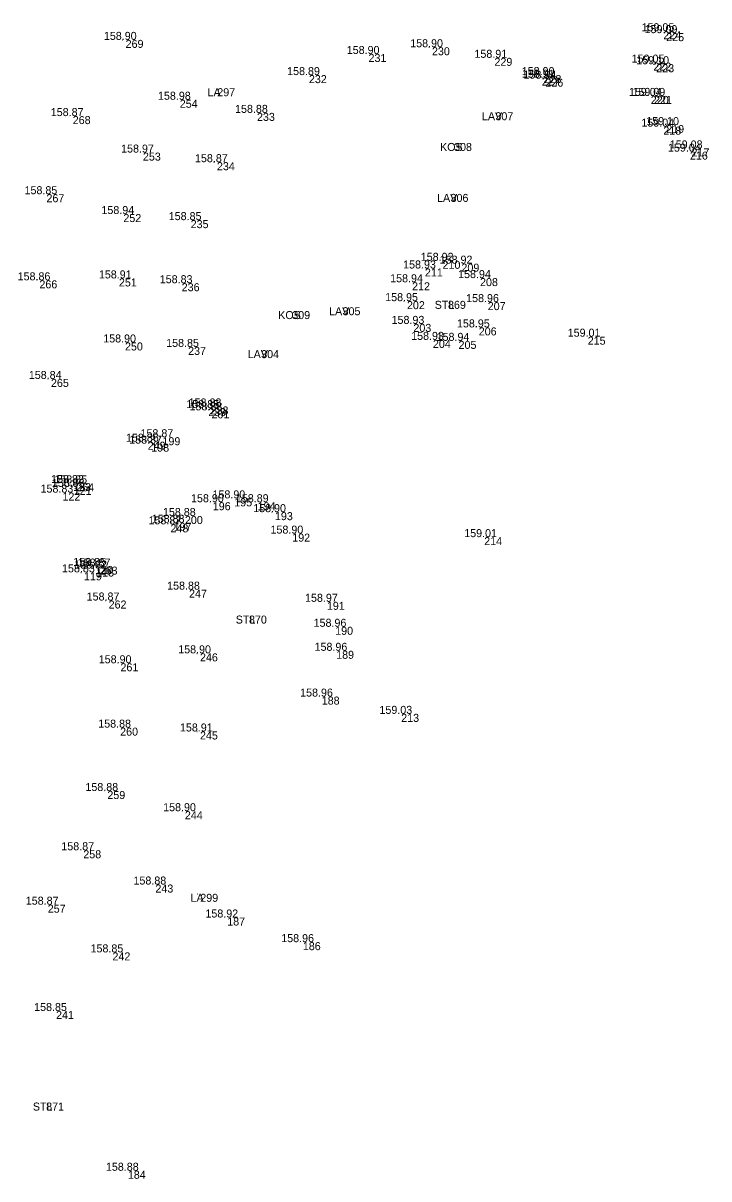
# Model space of a CAD drawing. Extents: x -583198 to -582878, y -1211024 to -1210637.
# Drawn here: x -583157.8 to -583136.4, y -1210989.52 to -1210953.43 of the extents above; entities that cross this region are included whole.
import ezdxf

# ---------------------------------------------------------------- set-up
doc = ezdxf.new("R2010")
doc.units = 0
for name, color, linetype in [('1   Kódy', 7, 'Continuous'), ('4   Body podrobné', 7, 'Continuous'), ('5   Body podrobné - čísla', 7, 'Continuous'), ('6   Body podrobné - výšky', 7, 'Continuous')]:
    doc.layers.add(name, color=color, linetype=linetype)

msp = doc.modelspace()

# ---------------------------------------------------------------- linework, layer by layer
at = {"layer": '4   Body podrobné'}
for p, q in [((-583137.91, -1210953.68), (-583137.909, -1210953.68)), ((-583137.82, -1210953.74), (-583137.819, -1210953.74)), ((-583154.69, -1210953.95), (-583154.689, -1210953.95)), ((-583145.13, -1210954.18), (-583145.129, -1210954.18)), ((-583147.11, -1210954.39), (-583147.109, -1210954.39)), ((-583143.18, -1210954.51), (-583143.179, -1210954.51)), ((-583138.22, -1210954.66), (-583138.219, -1210954.66)), ((-583138.13, -1210954.71), (-583138.129, -1210954.71)), ((-583148.97, -1210955.05), (-583148.969, -1210955.05)), ((-583141.7, -1210955.13), (-583141.699, -1210955.13)), ((-583141.65, -1210955.05), (-583141.649, -1210955.05)), ((-583141.59, -1210955.16), (-583141.589, -1210955.16)), ((-583151.83, -1210955.46), (-583151.829, -1210955.46)), ((-583153, -1210955.82), (-583152.999, -1210955.82)), ((-583138.3, -1210955.7), (-583138.299, -1210955.7)), ((-583138.2, -1210955.7), (-583138.199, -1210955.7)), ((-583156.34, -1210956.33), (-583156.339, -1210956.33)), ((-583150.59, -1210956.23), (-583150.589, -1210956.23)), ((-583143.15, -1210956.21), (-583143.149, -1210956.21)), ((-583137.91, -1210956.66), (-583137.909, -1210956.66)), ((-583137.82, -1210956.61), (-583137.819, -1210956.61)), ((-583144.44, -1210957.17), (-583144.439, -1210957.17)), ((-583137.03, -1210957.34), (-583137.029, -1210957.34)), ((-583154.15, -1210957.47), (-583154.149, -1210957.47)), ((-583151.84, -1210957.77), (-583151.839, -1210957.77)), ((-583137.08, -1210957.44), (-583137.079, -1210957.44)), ((-583157.16, -1210958.77), (-583157.159, -1210958.77)), ((-583144.55, -1210958.76), (-583144.549, -1210958.76)), ((-583154.76, -1210959.39), (-583154.759, -1210959.39)), ((-583152.66, -1210959.58), (-583152.659, -1210959.58)), ((-583144.8, -1210960.85), (-583144.799, -1210960.85)), ((-583144.21, -1210960.94), (-583144.209, -1210960.94)), ((-583154.9, -1210961.4), (-583154.899, -1210961.4)), ((-583145.35, -1210961.09), (-583145.349, -1210961.09)), ((-583143.63, -1210961.39), (-583143.629, -1210961.39)), ((-583157.38, -1210961.46), (-583157.379, -1210961.46)), ((-583152.94, -1210961.55), (-583152.939, -1210961.55)), ((-583145.75, -1210961.52), (-583145.749, -1210961.52)), ((-583145.91, -1210962.11), (-583145.909, -1210962.11)), ((-583144.63, -1210962.1), (-583144.629, -1210962.1)), ((-583149.49, -1210962.42), (-583149.489, -1210962.42)), ((-583147.92, -1210962.3), (-583147.919, -1210962.3)), ((-583143.39, -1210962.14), (-583143.389, -1210962.14)), ((-583145.71, -1210962.82), (-583145.709, -1210962.82)), ((-583143.67, -1210962.93), (-583143.669, -1210962.93)), ((-583154.71, -1210963.4), (-583154.709, -1210963.4)), ((-583152.74, -1210963.54), (-583152.739, -1210963.54)), ((-583145.1, -1210963.32), (-583145.099, -1210963.32)), ((-583144.3, -1210963.35), (-583144.299, -1210963.35)), ((-583140.27, -1210963.22), (-583140.269, -1210963.22)), ((-583150.46, -1210963.64), (-583150.459, -1210963.64)), ((-583157.02, -1210964.54), (-583157.019, -1210964.54)), ((-583152.11, -1210965.45), (-583152.109, -1210965.45)), ((-583152.04, -1210965.4), (-583152.039, -1210965.4)), ((-583152.01, -1210965.52), (-583152.009, -1210965.52)), ((-583153.54, -1210966.36), (-583153.539, -1210966.36)), ((-583154, -1210966.5), (-583153.999, -1210966.5)), ((-583153.89, -1210966.56), (-583153.889, -1210966.56)), ((-583156.33, -1210967.79), (-583156.329, -1210967.79)), ((-583156.23, -1210967.8), (-583156.229, -1210967.8)), ((-583156.66, -1210968.09), (-583156.659, -1210968.09)), ((-583156.31, -1210967.91), (-583156.309, -1210967.91)), ((-583151.97, -1210968.39), (-583151.969, -1210968.39)), ((-583151.3, -1210968.27), (-583151.299, -1210968.27)), ((-583150.57, -1210968.39), (-583150.569, -1210968.39)), ((-583152.84, -1210968.82), (-583152.839, -1210968.82)), ((-583150.03, -1210968.7), (-583150.029, -1210968.7)), ((-583153.29, -1210969.08), (-583153.289, -1210969.08)), ((-583153.19, -1210969.03), (-583153.189, -1210969.03)), ((-583149.49, -1210969.37), (-583149.489, -1210969.37)), ((-583143.5, -1210969.48), (-583143.499, -1210969.48)), ((-583155.64, -1210970.38), (-583155.639, -1210970.38)), ((-583155.5, -1210970.4), (-583155.499, -1210970.4)), ((-583155.99, -1210970.58), (-583155.989, -1210970.58)), ((-583155.61, -1210970.46), (-583155.609, -1210970.46)), ((-583152.71, -1210971.12), (-583152.709, -1210971.12)), ((-583155.22, -1210971.46), (-583155.219, -1210971.46)), ((-583148.41, -1210971.5), (-583148.409, -1210971.5)), ((-583150.84, -1210971.93), (-583150.839, -1210971.93)), ((-583148.15, -1210972.28), (-583148.149, -1210972.28)), ((-583152.37, -1210973.11), (-583152.369, -1210973.11)), ((-583148.12, -1210973.03), (-583148.119, -1210973.03)), ((-583154.85, -1210973.42), (-583154.849, -1210973.42)), ((-583148.57, -1210974.46), (-583148.569, -1210974.46)), ((-583146.09, -1210975), (-583146.089, -1210975)), ((-583154.86, -1210975.43), (-583154.859, -1210975.43)), ((-583152.37, -1210975.55), (-583152.369, -1210975.55)), ((-583155.26, -1210977.41), (-583155.259, -1210977.41)), ((-583152.84, -1210978.04), (-583152.839, -1210978.04)), ((-583156.01, -1210979.26), (-583156.009, -1210979.26)), ((-583153.76, -1210980.33), (-583153.759, -1210980.33)), ((-583152.36, -1210980.62), (-583152.359, -1210980.62)), ((-583157.12, -1210980.96), (-583157.119, -1210980.96)), ((-583151.52, -1210981.36), (-583151.519, -1210981.36)), ((-583149.16, -1210982.13), (-583149.159, -1210982.13)), ((-583155.1, -1210982.45), (-583155.099, -1210982.45)), ((-583156.86, -1210984.28), (-583156.859, -1210984.28)), ((-583157.17, -1210987.14), (-583157.169, -1210987.14)), ((-583154.62, -1210989.27), (-583154.619, -1210989.27))]:
    msp.add_line(p, q, dxfattribs=at)

# ---------------------------------------------------------------- texts
at = {"layer": '1   Kódy'}
for s, p in [('LA', (-583152.04, -1210955.71)), ('LAV', (-583143.478, -1210956.46)), ('KOS', (-583144.785, -1210957.42)), ('LAV', (-583144.878, -1210959.01)), ('STL', (-583144.952, -1210962.35)), ('KOS', (-583149.835, -1210962.67)), ('LAV', (-583148.248, -1210962.55)), ('LAV', (-583150.788, -1210963.89)), ('STL', (-583151.162, -1210972.18)), ('LA', (-583152.57, -1210980.87)), ('STL', (-583157.492, -1210987.39))]:
    msp.add_text(s, height=0.25, dxfattribs=at).set_placement(p)
at = {"layer": '5   Body podrobné - čísla'}
for s, p in [(' 224', (-583137.91, -1210953.93)), (' 225', (-583137.82, -1210953.99)), (' 269', (-583154.69, -1210954.2)), (' 230', (-583145.13, -1210954.43)), (' 231', (-583147.11, -1210954.64)), (' 229', (-583143.18, -1210954.76)), (' 222', (-583138.22, -1210954.91)), (' 223', (-583138.13, -1210954.96)), (' 232', (-583148.97, -1210955.3)), (' 227', (-583141.7, -1210955.38)), (' 228', (-583141.65, -1210955.3)), (' 226', (-583141.59, -1210955.41)), (' 297', (-583151.83, -1210955.71)), (' 254', (-583153, -1210956.07)), (' 220', (-583138.3, -1210955.95)), (' 221', (-583138.2, -1210955.95)), (' 268', (-583156.34, -1210956.58)), (' 233', (-583150.59, -1210956.48)), (' 307', (-583143.15, -1210956.46)), (' 218', (-583137.91, -1210956.91)), (' 219', (-583137.82, -1210956.86)), (' 308', (-583144.44, -1210957.42)), (' 216', (-583137.08, -1210957.69)), (' 217', (-583137.03, -1210957.59)), (' 253', (-583154.15, -1210957.72)), (' 234', (-583151.84, -1210958.02)), (' 267', (-583157.16, -1210959.02)), (' 306', (-583144.55, -1210959.01)), (' 252', (-583154.76, -1210959.64)), (' 235', (-583152.66, -1210959.83)), (' 210', (-583144.8, -1210961.1)), (' 209', (-583144.21, -1210961.19)), (' 251', (-583154.9, -1210961.65)), (' 211', (-583145.35, -1210961.34)), (' 208', (-583143.63, -1210961.64)), (' 266', (-583157.38, -1210961.71)), (' 236', (-583152.94, -1210961.8)), (' 212', (-583145.75, -1210961.77)), (' 202', (-583145.91, -1210962.36)), (' 869', (-583144.63, -1210962.35)), (' 309', (-583149.49, -1210962.67)), (' 305', (-583147.92, -1210962.55)), (' 207', (-583143.39, -1210962.39)), (' 203', (-583145.71, -1210963.07)), (' 206', (-583143.67, -1210963.18)), (' 250', (-583154.71, -1210963.65)), (' 237', (-583152.74, -1210963.79)), (' 204', (-583145.1, -1210963.57)), (' 205', (-583144.3, -1210963.6)), (' 215', (-583140.27, -1210963.47)), (' 304', (-583150.46, -1210963.89)), (' 265', (-583157.02, -1210964.79)), (' 239', (-583152.11, -1210965.7)), (' 238', (-583152.04, -1210965.65)), (' 201', (-583152.01, -1210965.77)), (' 199', (-583153.54, -1210966.61)), (' 249', (-583154, -1210966.75)), (' 198', (-583153.89, -1210966.81)), (' 123', (-583156.33, -1210968.04)), (' 121', (-583156.31, -1210968.16)), (' 264', (-583156.23, -1210968.05)), (' 122', (-583156.66, -1210968.34)), (' 195', (-583151.3, -1210968.52)), (' 196', (-583151.97, -1210968.64)), (' 194', (-583150.57, -1210968.64)), (' 200', (-583152.84, -1210969.07)), (' 193', (-583150.03, -1210968.95)), (' 248', (-583153.29, -1210969.33)), (' 197', (-583153.19, -1210969.28)), (' 192', (-583149.49, -1210969.62)), (' 214', (-583143.5, -1210969.73)), (' 120', (-583155.64, -1210970.63)), (' 263', (-583155.5, -1210970.65)), (' 119', (-583155.99, -1210970.83)), (' 118', (-583155.61, -1210970.71)), (' 247', (-583152.71, -1210971.37)), (' 262', (-583155.22, -1210971.71)), (' 191', (-583148.41, -1210971.75)), (' 870', (-583150.84, -1210972.18)), (' 190', (-583148.15, -1210972.53)), (' 246', (-583152.37, -1210973.36)), (' 189', (-583148.12, -1210973.28)), (' 261', (-583154.85, -1210973.67)), (' 188', (-583148.57, -1210974.71)), (' 213', (-583146.09, -1210975.25)), (' 260', (-583154.86, -1210975.68)), (' 245', (-583152.37, -1210975.8)), (' 259', (-583155.26, -1210977.66)), (' 244', (-583152.84, -1210978.29)), (' 258', (-583156.01, -1210979.51)), (' 243', (-583153.76, -1210980.58)), (' 299', (-583152.36, -1210980.87)), (' 257', (-583157.12, -1210981.21)), (' 187', (-583151.52, -1210981.61)), (' 186', (-583149.16, -1210982.38)), (' 242', (-583155.1, -1210982.7)), (' 241', (-583156.86, -1210984.53)), (' 871', (-583157.17, -1210987.39)), (' 184', (-583154.62, -1210989.52))]:
    msp.add_text(s, height=0.25, dxfattribs=at).set_placement(p)
at = {"layer": '6   Body podrobné - výšky'}
for s, p in [('159.05', (-583138.496, -1210953.68)), ('158.90', (-583155.276, -1210953.95)), ('159.09', (-583138.4, -1210953.74)), ('158.90', (-583147.696, -1210954.39)), ('158.90', (-583145.716, -1210954.18)), ('158.91', (-583143.712, -1210954.51)), ('159.05', (-583138.806, -1210954.66)), ('159.10', (-583138.661, -1210954.71)), ('158.89', (-583149.557, -1210955.05)), ('158.90', (-583142.236, -1210955.05)), ('158.91', (-583142.232, -1210955.13)), ('158.94', (-583142.182, -1210955.16)), ('158.98', (-583153.587, -1210955.82)), ('159.04', (-583138.891, -1210955.7)), ('159.09', (-583138.78, -1210955.7)), ('158.88', (-583151.182, -1210956.23)), ('158.87', (-583156.933, -1210956.33)), ('159.04', (-583138.501, -1210956.66)), ('159.10', (-583138.351, -1210956.61)), ('158.97', (-583154.738, -1210957.47)), ('159.04', (-583137.671, -1210957.44)), ('159.08', (-583137.616, -1210957.34)), ('158.87', (-583152.433, -1210957.77)), ('158.85', (-583157.752, -1210958.77)), ('158.94', (-583155.352, -1210959.39)), ('158.85', (-583153.252, -1210959.58)), ('158.92', (-583145.387, -1210960.85)), ('158.92', (-583144.797, -1210960.94)), ('158.93', (-583145.937, -1210961.09)), ('158.86', (-583157.967, -1210961.46)), ('158.91', (-583155.432, -1210961.4)), ('158.83', (-583153.532, -1210961.55)), ('158.94', (-583146.342, -1210961.52)), ('158.94', (-583144.222, -1210961.39)), ('158.95', (-583146.497, -1210962.11)), ('158.96', (-583143.971, -1210962.14)), ('158.93', (-583146.297, -1210962.82)), ('158.95', (-583144.257, -1210962.93)), ('158.90', (-583155.296, -1210963.4)), ('158.93', (-583145.687, -1210963.32)), ('158.94', (-583144.892, -1210963.35)), ('159.01', (-583140.801, -1210963.22)), ('158.85', (-583153.332, -1210963.54)), ('158.84', (-583157.618, -1210964.54)), ('158.85', (-583152.702, -1210965.45)), ('158.88', (-583152.632, -1210965.4)), ('158.88', (-583152.602, -1210965.52)), ('158.86', (-583154.587, -1210966.5)), ('158.87', (-583154.483, -1210966.56)), ('158.87', (-583154.133, -1210966.36)), ('158.82', (-583156.922, -1210967.79)), ('158.83', (-583157.252, -1210968.09)), ('158.83', (-583156.902, -1210967.91)), ('158.85', (-583156.822, -1210967.8)), ('158.90', (-583152.556, -1210968.39)), ('158.90', (-583151.886, -1210968.27)), ('158.89', (-583151.157, -1210968.39)), ('158.88', (-583153.432, -1210968.82)), ('158.90', (-583150.616, -1210968.7)), ('158.87', (-583153.883, -1210969.08)), ('158.88', (-583153.782, -1210969.03)), ('158.90', (-583150.076, -1210969.37)), ('159.01', (-583144.031, -1210969.48)), ('158.83', (-583156.582, -1210970.58)), ('158.85', (-583156.232, -1210970.38)), ('158.82', (-583156.202, -1210970.46)), ('158.87', (-583156.093, -1210970.4)), ('158.88', (-583153.302, -1210971.12)), ('158.87', (-583155.813, -1210971.46)), ('158.97', (-583148.998, -1210971.5)), ('158.96', (-583148.731, -1210972.28)), ('158.90', (-583152.956, -1210973.11)), ('158.96', (-583148.701, -1210973.03)), ('158.90', (-583155.436, -1210973.42)), ('158.96', (-583149.151, -1210974.46)), ('159.03', (-583146.676, -1210975)), ('158.88', (-583155.452, -1210975.43)), ('158.91', (-583152.902, -1210975.55)), ('158.88', (-583155.852, -1210977.41)), ('158.90', (-583153.426, -1210978.04)), ('158.87', (-583156.603, -1210979.26)), ('158.88', (-583154.352, -1210980.33)), ('158.87', (-583157.713, -1210980.96)), ('158.92', (-583152.107, -1210981.36)), ('158.96', (-583149.741, -1210982.13)), ('158.85', (-583155.692, -1210982.45)), ('158.85', (-583157.452, -1210984.28)), ('158.88', (-583155.212, -1210989.27))]:
    msp.add_text(s, height=0.25, dxfattribs=at).set_placement(p)

doc.saveas('drawing.dxf')
